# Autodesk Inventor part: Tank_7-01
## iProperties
Created: 2007-04
Part Number: Tank_7-01
Document SubType Name: Modeling
Designer: Admin
Density: 1 g/cm^3
Strap_Between: 660.000 mm
Strap_Width: 55.000 mm
Length: 1100.000 mm
Diameter: 620.000 mm
Author: Admin
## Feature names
1. Revolution1
2. Revolution2
3. Fillet1
4. Shell1
